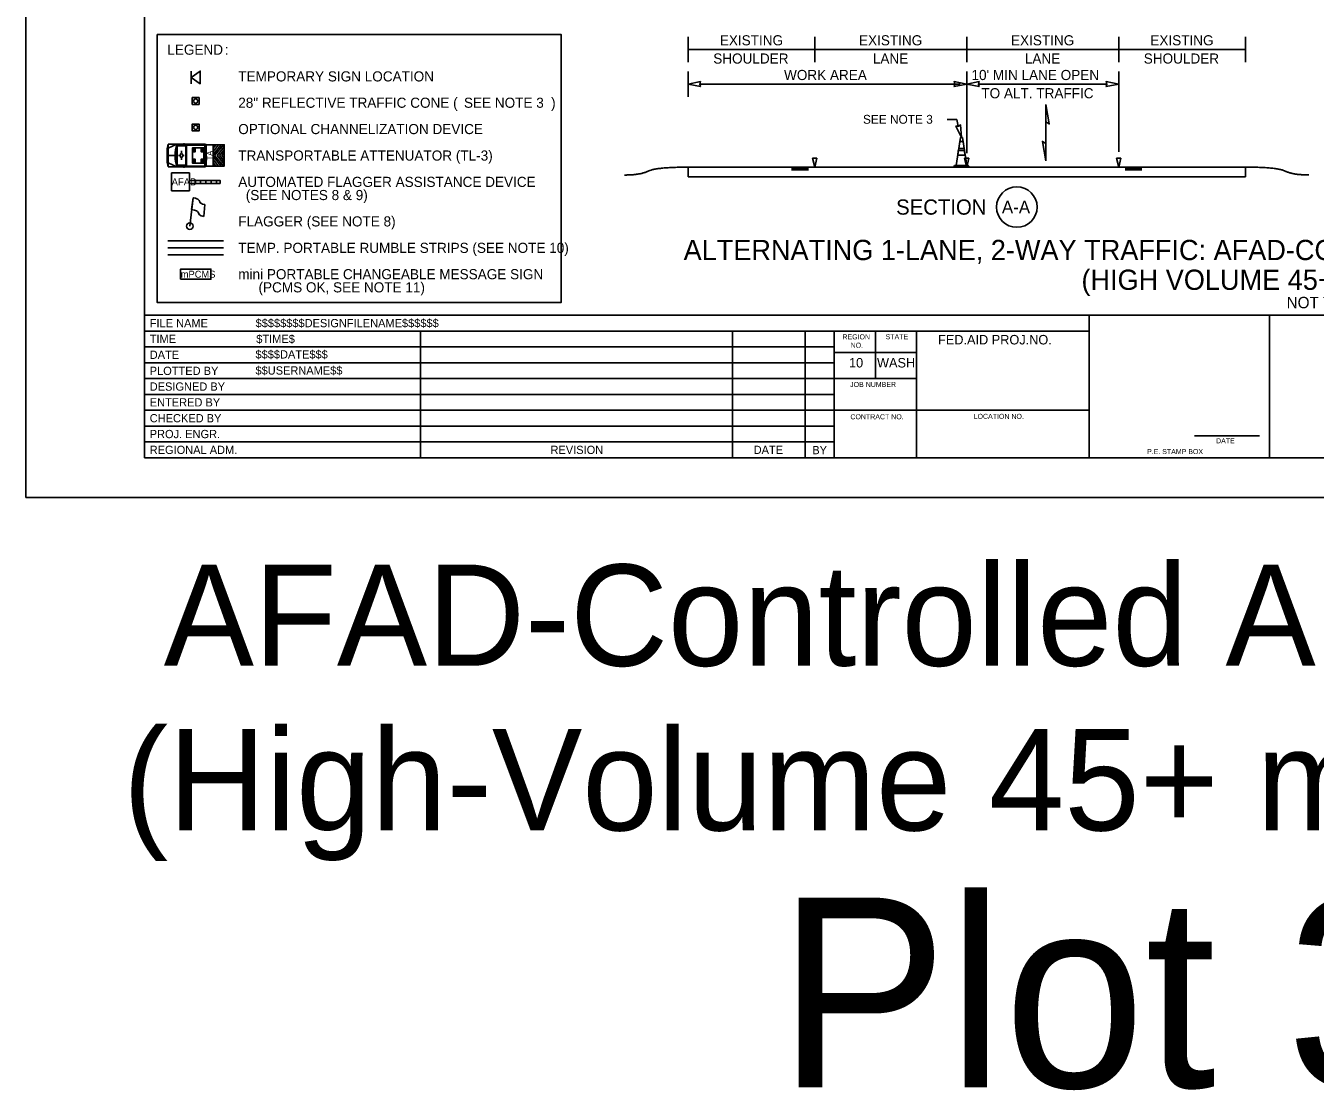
# Model space of a CAD drawing. Extents: x 99999.1 to 100095.7, y 99995 to 100010.7.
# Drawn here: x 100039.06 to 100049.24, y 99995.01 to 100003.41 of the extents above; entities that cross this region are included whole.
import ezdxf

# ---------------------------------------------------------------- set-up
doc = ezdxf.new("R2010")
doc.units = 0
for name, color, linetype in [('SH_DE_DetailHeading1Text', 7, 'Continuous'), ('SH_GI_PlotLimits', 7, 'Continuous'), ('SH_GI_SheetBorder', 7, 'Continuous'), ('SH_GI_SheetLocationText', 7, 'Continuous'), ('SH_GI_SheetTextInCells', 7, 'Continuous'), ('SH_GI_TitleBlockText', 7, 'Continuous'), ('TR_WZ_AFAD', 7, 'Continuous'), ('TR_WZ_FlaggingStation', 7, 'Continuous'), ('TR_WZ_PCMS', 7, 'Continuous'), ('TR_WZ_PortableSignMountBlk-Org', 7, 'Continuous'), ('TR_WZ_TrafficCone', 7, 'Continuous'), ('TR_WZ_TrafficConeElev', 7, 'Continuous'), ('TR_WZ_TransportableAttenuator', 7, 'Continuous'), ('TR_WZ_WorkZoneDetails', 7, 'Continuous'), ('TR_WZ_WorkZoneTextCurrent', 7, 'Continuous')]:
    doc.layers.add(name, color=color, linetype=linetype)

msp = doc.modelspace()

# ---------------------------------------------------------------- linework, layer by layer
at = {"layer": 'SH_GI_PlotLimits'}
msp.add_lwpolyline([(100039.062, 99999.687), (100056.062, 99999.687), (100056.062, 100010.687), (100039.062, 100010.687)], close=True, dxfattribs=at)
at = {"layer": 'SH_GI_SheetBorder'}
for p, q in [((100040, 100010.375), (100040, 100000)), ((100040, 100001.126), (100055.75, 100001.126)), ((100047.457, 100000), (100047.457, 100001.126)), ((100048.883, 100000), (100048.883, 100001.126)), ((100040, 100001.001), (100047.457, 100001.001)), ((100042.179, 100001.001), (100042.179, 100000)), ((100044.641, 100001.001), (100044.641, 100000)), ((100045.216, 100001.001), (100045.216, 100000)), ((100045.445, 100001.001), (100045.445, 100000)), ((100045.772, 100000.625), (100045.772, 100001.001)), ((100046.096, 100000), (100046.096, 100001.001)), ((100040, 100000.876), (100042.182, 100000.876)), ((100042.182, 100000.876), (100045.447, 100000.876)), ((100046.096, 100000.831), (100045.447, 100000.831)), ((100040, 100000.751), (100042.182, 100000.751)), ((100042.182, 100000.751), (100045.447, 100000.751)), ((100040, 100000.625), (100045.447, 100000.625)), ((100046.096, 100000.625), (100045.447, 100000.625)), ((100040, 100000.5), (100045.447, 100000.5)), ((100040, 100000.375), (100045.447, 100000.375)), ((100047.457, 100000.375), (100045.447, 100000.375)), ((100040, 100000.25), (100045.447, 100000.25)), ((100040, 100000.125), (100045.447, 100000.125)), ((100048.29, 100000.173), (100048.802, 100000.173)), ((100040, 100000), (100055.75, 100000))]:
    msp.add_line(p, q, dxfattribs=at)
at = {"layer": 'TR_WZ_AFAD'}
for p, q in [((100040.212, 100002.107), (100040.212, 100002.251)), ((100040.212, 100002.251), (100040.356, 100002.251)), ((100040.356, 100002.251), (100040.212, 100002.251)), ((100040.212, 100002.251), (100040.212, 100002.107)), ((100040.356, 100002.251), (100040.356, 100002.107)), ((100040.356, 100002.184), (100040.356, 100002.251)), ((100040.399, 100002.191), (100040.356, 100002.191)), ((100040.356, 100002.191), (100040.356, 100002.184)), ((100040.356, 100002.184), (100040.356, 100002.179)), ((100040.441, 100002.191), (100040.399, 100002.191)), ((100040.399, 100002.167), (100040.441, 100002.167)), ((100040.484, 100002.191), (100040.441, 100002.191)), ((100040.441, 100002.179), (100040.441, 100002.191)), ((100040.441, 100002.167), (100040.441, 100002.179)), ((100040.441, 100002.167), (100040.484, 100002.167)), ((100040.527, 100002.191), (100040.484, 100002.191)), ((100040.484, 100002.191), (100040.484, 100002.179)), ((100040.484, 100002.179), (100040.484, 100002.167)), ((100040.484, 100002.167), (100040.527, 100002.167)), ((100040.569, 100002.191), (100040.527, 100002.191)), ((100040.527, 100002.179), (100040.527, 100002.191)), ((100040.527, 100002.167), (100040.527, 100002.179)), ((100040.527, 100002.167), (100040.569, 100002.167)), ((100040.569, 100002.191), (100040.569, 100002.179)), ((100040.569, 100002.179), (100040.569, 100002.167)), ((100040.569, 100002.167), (100040.596, 100002.167)), ((100040.356, 100002.107), (100040.212, 100002.107)), ((100040.212, 100002.107), (100040.356, 100002.107))]:
    msp.add_line(p, q, dxfattribs=at)
for points in [[(100040.356, 100002.167), (100040.596, 100002.167), (100040.596, 100002.191), (100040.356, 100002.191)], [(100040.356, 100002.107), (100040.356, 100002.174), (100040.356, 100002.184)], [(100040.356, 100002.179), (100040.356, 100002.174), (100040.356, 100002.167), (100040.399, 100002.167)], [(100040.399, 100002.167), (100040.399, 100002.179), (100040.399, 100002.191)], [(100040.399, 100002.191), (100040.399, 100002.179), (100040.399, 100002.167)], [(100040.441, 100002.191), (100040.441, 100002.179), (100040.441, 100002.167)], [(100040.484, 100002.167), (100040.484, 100002.179), (100040.484, 100002.191)], [(100040.527, 100002.191), (100040.527, 100002.179), (100040.527, 100002.167)], [(100040.569, 100002.167), (100040.569, 100002.179), (100040.569, 100002.191)], [(100040.596, 100002.167), (100040.596, 100002.191), (100040.569, 100002.191)]]:
    msp.add_lwpolyline(points, dxfattribs=at)
at = {"layer": 'TR_WZ_FlaggingStation'}
for p, q in [((100040.357, 100001.829), (100040.383, 100002.053)), ((100040.372, 100001.962), (100040.383, 100002.054)), ((100040.372, 100001.962), (100040.372, 100001.962)), ((100040.477, 100001.999), (100040.467, 100001.906))]:
    msp.add_line(p, q, dxfattribs=at)
for points in [[(100040.383, 100002.054), (100040.387, 100002.053), (100040.402, 100002.05), (100040.413, 100002.046), (100040.42, 100002.042), (100040.427, 100002.038), (100040.432, 100002.032), (100040.435, 100002.026), (100040.436, 100002.021), (100040.44, 100002.014), (100040.449, 100002.008), (100040.458, 100002.004), (100040.477, 100001.999)], [(100040.467, 100001.906), (100040.46, 100001.907), (100040.446, 100001.91), (100040.433, 100001.919), (100040.428, 100001.927), (100040.425, 100001.935), (100040.418, 100001.944), (100040.409, 100001.949), (100040.395, 100001.955), (100040.372, 100001.962)]]:
    msp.add_lwpolyline(points, dxfattribs=at)
msp.add_circle((100040.357, 100001.829), 0.026, dxfattribs=at)
at = {"layer": 'TR_WZ_PCMS'}
msp.add_lwpolyline([(100040.284, 100001.41), (100040.524, 100001.41), (100040.524, 100001.49), (100040.284, 100001.49)], close=True, dxfattribs=at)
msp.add_lwpolyline([(100040.284, 100001.41), (100040.524, 100001.41), (100040.524, 100001.49), (100040.284, 100001.49), (100040.284, 100001.41)], dxfattribs=at)
at = {"layer": 'TR_WZ_PortableSignMountBlk-Org'}
msp.add_line((100040.368, 100002.954), (100040.368, 100003.054), dxfattribs=at)
msp.add_lwpolyline([(100040.368, 100003.004), (100040.44, 100003.054), (100040.44, 100002.954)], close=True, dxfattribs=at)
at = {"layer": 'TR_WZ_TrafficCone'}
for points in [[(100040.377, 100002.844), (100040.431, 100002.844), (100040.431, 100002.79), (100040.377, 100002.79), (100040.377, 100002.844)], [(100040.377, 100002.79), (100040.431, 100002.79), (100040.431, 100002.844), (100040.377, 100002.844), (100040.377, 100002.79)], [(100040.377, 100002.635), (100040.431, 100002.635), (100040.431, 100002.582), (100040.377, 100002.582), (100040.377, 100002.635)], [(100040.377, 100002.582), (100040.431, 100002.582), (100040.431, 100002.635), (100040.377, 100002.635), (100040.377, 100002.582)]]:
    msp.add_lwpolyline(points, dxfattribs=at)
for centre in [(100040.404, 100002.817), (100040.404, 100002.609)]:
    msp.add_circle(centre, 0.0167, dxfattribs=at)
at = {"layer": 'TR_WZ_TrafficConeElev'}
for p, q in [((100046.436, 100002.498), (100046.428, 100002.443)), ((100046.428, 100002.443), (100046.47, 100002.443)), ((100046.462, 100002.498), (100046.436, 100002.498)), ((100046.47, 100002.443), (100046.462, 100002.498)), ((100046.425, 100002.427), (100046.42, 100002.389)), ((100046.42, 100002.389), (100046.478, 100002.389)), ((100046.472, 100002.427), (100046.425, 100002.427)), ((100046.478, 100002.389), (100046.472, 100002.427)), ((100046.395, 100002.308), (100046.391, 100002.304)), ((100046.391, 100002.304), (100046.391, 100002.296)), ((100046.391, 100002.296), (100046.507, 100002.296)), ((100046.407, 100002.308), (100046.395, 100002.308)), ((100046.507, 100002.304), (100046.503, 100002.308)), ((100046.507, 100002.296), (100046.507, 100002.304))]:
    msp.add_line(p, q, dxfattribs=at)
msp.add_lwpolyline([(100046.407, 100002.308), (100046.491, 100002.308), (100046.457, 100002.529), (100046.441, 100002.529)], close=True, dxfattribs=at)
msp.add_lwpolyline([(100046.407, 100002.308), (100046.491, 100002.308), (100046.457, 100002.529), (100046.441, 100002.529)], close=True, dxfattribs=at)
msp.add_lwpolyline([(100046.503, 100002.308), (100046.491, 100002.308), (100046.407, 100002.308)], dxfattribs=at)
at = {"layer": 'TR_WZ_TransportableAttenuator'}
for p, q in [((100040.186, 100002.477), (100040.179, 100002.441)), ((100040.179, 100002.334), (100040.179, 100002.441)), ((100040.186, 100002.297), (100040.186, 100002.477)), ((100040.186, 100002.477), (100040.326, 100002.477)), ((100040.186, 100002.444), (100040.256, 100002.477)), ((100040.256, 100002.297), (100040.256, 100002.477)), ((100040.257, 100002.297), (100040.257, 100002.477)), ((100040.265, 100002.463), (100040.257, 100002.477)), ((100040.257, 100002.463), (100040.326, 100002.463)), ((100040.307, 100002.48), (100040.315, 100002.48)), ((100040.326, 100002.297), (100040.326, 100002.477)), ((100040.48, 100002.477), (100040.328, 100002.477)), ((100040.328, 100002.297), (100040.328, 100002.477)), ((100040.476, 100002.47), (100040.332, 100002.47)), ((100040.332, 100002.304), (100040.332, 100002.47)), ((100040.476, 100002.304), (100040.476, 100002.47)), ((100040.48, 100002.297), (100040.48, 100002.477)), ((100040.48, 100002.472), (100040.541, 100002.472)), ((100040.48, 100002.303), (100040.48, 100002.472)), ((100040.484, 100002.474), (100040.481, 100002.474)), ((100040.481, 100002.3), (100040.481, 100002.474)), ((100040.487, 100002.306), (100040.487, 100002.469)), ((100040.541, 100002.472), (100040.541, 100002.303)), ((100040.541, 100002.395), (100040.605, 100002.472)), ((100040.541, 100002.444), (100040.564, 100002.472)), ((100040.584, 100002.472), (100040.541, 100002.42)), ((100040.605, 100002.472), (100040.541, 100002.395)), ((100040.541, 100002.42), (100040.584, 100002.472)), ((100040.564, 100002.472), (100040.541, 100002.444)), ((100040.541, 100002.42), (100040.541, 100002.444)), ((100040.541, 100002.444), (100040.541, 100002.42)), ((100040.623, 100002.472), (100040.553, 100002.387)), ((100040.553, 100002.387), (100040.623, 100002.472)), ((100040.564, 100002.472), (100040.584, 100002.472)), ((100040.584, 100002.472), (100040.564, 100002.472)), ((100040.573, 100002.387), (100040.629, 100002.455)), ((100040.629, 100002.455), (100040.573, 100002.387)), ((100040.605, 100002.472), (100040.623, 100002.472)), ((100040.623, 100002.472), (100040.605, 100002.472)), ((100040.629, 100002.455), (100040.629, 100002.432)), ((100040.629, 100002.432), (100040.629, 100002.455)), ((100040.186, 100002.387), (100040.242, 100002.387)), ((100040.268, 100002.387), (100040.278, 100002.387)), ((100040.291, 100002.423), (100040.291, 100002.408)), ((100040.291, 100002.352), (100040.291, 100002.366)), ((100040.301, 100002.388), (100040.301, 100002.388)), ((100040.313, 100002.387), (100040.304, 100002.387)), ((100040.487, 100002.4), (100040.481, 100002.397)), ((100040.487, 100002.375), (100040.481, 100002.378)), ((100040.486, 100002.387), (100040.483, 100002.387)), ((100040.484, 100002.385), (100040.484, 100002.39)), ((100040.541, 100002.38), (100040.541, 100002.395)), ((100040.541, 100002.395), (100040.541, 100002.38)), ((100040.604, 100002.303), (100040.541, 100002.38)), ((100040.541, 100002.38), (100040.604, 100002.303)), ((100040.541, 100002.355), (100040.583, 100002.303)), ((100040.541, 100002.331), (100040.541, 100002.355)), ((100040.583, 100002.303), (100040.541, 100002.355)), ((100040.541, 100002.355), (100040.541, 100002.331)), ((100040.553, 100002.387), (100040.623, 100002.303)), ((100040.623, 100002.303), (100040.553, 100002.387)), ((100040.629, 100002.319), (100040.573, 100002.387)), ((100040.573, 100002.387), (100040.629, 100002.319)), ((100040.629, 100002.432), (100040.591, 100002.386)), ((100040.591, 100002.386), (100040.629, 100002.432)), ((100040.591, 100002.386), (100040.629, 100002.341)), ((100040.629, 100002.341), (100040.591, 100002.386)), ((100040.61, 100002.387), (100040.629, 100002.411)), ((100040.629, 100002.411), (100040.61, 100002.387)), ((100040.629, 100002.364), (100040.61, 100002.387)), ((100040.61, 100002.387), (100040.629, 100002.364)), ((100040.629, 100002.411), (100040.629, 100002.364)), ((100040.629, 100002.364), (100040.629, 100002.411)), ((100040.629, 100002.341), (100040.629, 100002.319)), ((100040.629, 100002.319), (100040.629, 100002.341)), ((100040.186, 100002.297), (100040.179, 100002.334)), ((100040.186, 100002.33), (100040.256, 100002.297)), ((100040.186, 100002.297), (100040.326, 100002.297)), ((100040.257, 100002.297), (100040.266, 100002.311)), ((100040.257, 100002.311), (100040.326, 100002.311)), ((100040.307, 100002.295), (100040.315, 100002.295)), ((100040.48, 100002.297), (100040.328, 100002.297)), ((100040.476, 100002.304), (100040.332, 100002.304)), ((100040.48, 100002.303), (100040.541, 100002.303)), ((100040.484, 100002.3), (100040.481, 100002.3)), ((100040.564, 100002.303), (100040.541, 100002.331)), ((100040.541, 100002.331), (100040.564, 100002.303)), ((100040.583, 100002.303), (100040.564, 100002.303)), ((100040.564, 100002.303), (100040.583, 100002.303)), ((100040.623, 100002.303), (100040.604, 100002.303)), ((100040.604, 100002.303), (100040.623, 100002.303))]:
    msp.add_line(p, q, dxfattribs=at)
for points in [[(100040.468, 100002.327), (100040.378, 100002.327), (100040.378, 100002.447), (100040.468, 100002.447)], [(100040.386, 100002.417), (100040.401, 100002.417), (100040.401, 100002.44), (100040.386, 100002.44)], [(100040.461, 100002.417), (100040.446, 100002.417), (100040.446, 100002.44), (100040.461, 100002.44)], [(100040.541, 100002.472), (100040.629, 100002.472), (100040.629, 100002.303), (100040.541, 100002.303)], [(100040.386, 100002.335), (100040.401, 100002.335), (100040.401, 100002.357), (100040.386, 100002.357)], [(100040.461, 100002.335), (100040.446, 100002.335), (100040.446, 100002.357), (100040.461, 100002.357)]]:
    msp.add_lwpolyline(points, close=True, dxfattribs=at)
msp.add_lwpolyline([(100040.541, 100002.303), (100040.629, 100002.303), (100040.629, 100002.472), (100040.541, 100002.472)], dxfattribs=at)
for centre, major_axis, start_param, end_param in [((100040.356, 100002.387), (0, -0.189), 4.215852, 5.209111), ((100040.484, 100002.469), (0, 0.00549), 4.712389, 6.283185), ((100040.484, 100002.306), (0, -0.00549), 6.283185, 7.853982)]:
    msp.add_ellipse(centre, major_axis=major_axis, ratio=0.60201, start_param=start_param, end_param=end_param, dxfattribs=at)
for centre, major_axis in [((100040.291, 100002.387), (0, 0.0173)), ((100040.484, 100002.387), (0, 0.00254))]:
    msp.add_ellipse(centre, major_axis=major_axis, ratio=0.60201, dxfattribs=at)
at = {"layer": 'TR_WZ_WorkZoneDetails'}
for p, q in [((100044.291, 100003.125), (100044.291, 100003.325)), ((100045.291, 100003.125), (100045.291, 100003.325)), ((100046.491, 100003.125), (100046.491, 100003.325)), ((100047.691, 100003.125), (100047.691, 100003.325)), ((100048.691, 100003.125), (100048.691, 100003.325)), ((100044.291, 100003.225), (100045.291, 100003.225)), ((100045.291, 100003.225), (100046.491, 100003.225)), ((100046.491, 100003.225), (100047.691, 100003.225)), ((100047.691, 100003.225), (100048.691, 100003.225)), ((100044.291, 100002.851), (100044.291, 100003.051)), ((100046.491, 100002.405), (100046.491, 100003.051)), ((100047.691, 100002.415), (100047.691, 100003.051)), ((100046.439, 100002.951), (100044.384, 100002.951)), ((100047.597, 100002.951), (100046.584, 100002.951)), ((100046.336, 100002.672), (100046.412, 100002.672)), ((100046.425, 100002.62), (100046.412, 100002.672)), ((100047.116, 100002.652), (100047.116, 100002.483)), ((100047.116, 100002.483), (100047.116, 100002.652)), ((100044.291, 100002.295), (100044.291, 100002.22)), ((100048.691, 100002.295), (100044.291, 100002.295)), ((100045.108, 100002.29), (100045.241, 100002.29)), ((100045.108, 100002.285), (100045.241, 100002.285)), ((100045.108, 100002.279), (100045.241, 100002.279)), ((100045.108, 100002.274), (100045.241, 100002.274)), ((100047.874, 100002.29), (100047.741, 100002.29)), ((100047.874, 100002.284), (100047.741, 100002.284)), ((100047.874, 100002.278), (100047.741, 100002.278)), ((100047.874, 100002.273), (100047.741, 100002.273)), ((100048.691, 100002.295), (100048.691, 100002.22)), ((100048.691, 100002.22), (100044.291, 100002.22)), ((100040.624, 100001.714), (100040.184, 100001.714)), ((100040.624, 100001.659), (100040.184, 100001.659)), ((100040.624, 100001.603), (100040.184, 100001.603))]:
    msp.add_line(p, q, dxfattribs=at)
for points in [[(100044.291, 100002.951), (100044.389, 100002.932), (100044.384, 100002.951), (100044.389, 100002.971)], [(100046.491, 100002.951), (100046.392, 100002.932), (100046.397, 100002.951), (100046.392, 100002.971)], [(100046.491, 100002.951), (100046.589, 100002.932), (100046.584, 100002.951), (100046.589, 100002.971)], [(100047.691, 100002.951), (100047.592, 100002.932), (100047.597, 100002.951), (100047.592, 100002.971)], [(100047.116, 100002.789), (100047.143, 100002.636), (100047.116, 100002.652)], [(100046.449, 100002.529), (100046.406, 100002.619), (100046.426, 100002.62), (100046.443, 100002.629)], [(100047.116, 100002.345), (100047.089, 100002.499), (100047.116, 100002.483)], [(100045.291, 100002.295), (100045.274, 100002.365), (100045.307, 100002.365)], [(100046.491, 100002.295), (100046.474, 100002.365), (100046.507, 100002.365)], [(100047.691, 100002.295), (100047.674, 100002.365), (100047.707, 100002.365)]]:
    msp.add_lwpolyline(points, close=True, dxfattribs=at)
for points in [[(100045.307, 100002.365), (100045.274, 100002.365), (100045.291, 100002.295), (100045.307, 100002.365)], [(100046.507, 100002.365), (100046.474, 100002.365), (100046.491, 100002.295), (100046.507, 100002.365)], [(100047.707, 100002.365), (100047.674, 100002.365), (100047.691, 100002.295), (100047.707, 100002.365)]]:
    msp.add_lwpolyline(points, dxfattribs=at)
msp.add_circle((100046.887, 100001.98), 0.16, dxfattribs=at)
for points in [[(100044.291, 100002.295), (100044.04, 100002.295), (100043.914, 100002.233), (100043.789, 100002.233)], [(100048.691, 100002.295), (100048.942, 100002.296), (100049.067, 100002.233), (100049.193, 100002.234)]]:
    msp.add_open_spline(points, degree=2, dxfattribs=at)
at = {"layer": 'TR_WZ_WorkZoneTextCurrent'}
msp.add_lwpolyline([(100040.1, 100003.343), (100043.289, 100003.343), (100043.289, 100001.226), (100040.1, 100001.226)], close=True, dxfattribs=at)

# ---------------------------------------------------------------- texts
at = {"layer": 'SH_DE_DetailHeading1Text'}
for s, height, p in [('ALTERNATING 1-LANE, 2-WAY TRAFFIC: AFAD-CONTROLLED + TEMPORARY RUMBLE STRIPS', 0.16, (100044.256, 100001.561)), ('(HIGH VOLUME 45+ MPH HIGHWAYS)', 0.16, (100047.397, 100001.326)), ('NOT TO SCALE', 0.09, (100049.017, 100001.181))]:
    msp.add_text(s, height=height, rotation=360, dxfattribs=at).set_placement(p)
at = {"layer": 'SH_GI_SheetLocationText'}
for s, height, p in [('AFAD-Controlled Alt Traffic + RS', 0.8, (100040.151, 99998.357)), ('(High-Volume 45+ mph Highways)', 0.8, (100039.83, 99997.057)), ('Plot 3', 1.5, (100045.001, 99995.027))]:
    msp.add_text(s, height=height, dxfattribs=at).set_placement(p)
at = {"layer": 'SH_GI_SheetTextInCells'}
for s, height, p in [('FILE NAME', 0.0651, (100040.041, 100001.031)), ('TIME', 0.0651, (100040.041, 100000.906)), ('REGION', 0.04, (100045.51, 100000.935)), ('STATE', 0.04, (100045.851, 100000.936)), ('FED.AID PROJ.NO.', 0.07506, (100046.265, 100000.895)), ('DATE', 0.0651, (100040.041, 100000.781)), ('NO.', 0.04, (100045.575, 100000.869)), ('PLOTTED BY', 0.0651, (100040.041, 100000.654)), ('10', 0.0751, (100045.562, 100000.713)), ('WASH', 0.0751, (100045.783, 100000.713)), ('DESIGNED BY', 0.06505, (100040.041, 100000.53)), ('JOB NUMBER', 0.04, (100045.571, 100000.559)), ('ENTERED BY', 0.0651, (100040.041, 100000.405)), ('CHECKED BY', 0.0651, (100040.041, 100000.28)), ('CONTRACT NO.', 0.04003, (100045.573, 100000.304)), ('LOCATION NO.', 0.04003, (100046.546, 100000.307)), ('PROJ. ENGR.', 0.06505, (100040.041, 100000.155)), ('DATE', 0.04, (100048.46, 100000.114)), ('REGIONAL ADM.', 0.06505, (100040.041, 100000.03)), ('REVISION', 0.0651, (100043.205, 100000.03)), ('DATE', 0.0651, (100044.809, 100000.03)), ('BY', 0.0651, (100045.272, 100000.028)), ('P.E. STAMP BOX', 0.04003, (100047.915, 100000.029))]:
    msp.add_text(s, height=height, dxfattribs=at).set_placement(p)
at = {"layer": 'SH_GI_TitleBlockText'}
for s, height, p in [('$$$$$$$$DESIGNFILENAME$$$$$$', 0.06505, (100040.877, 100001.031)), ('$TIME$', 0.0651, (100040.882, 100000.906)), ('$$$$DATE$$$', 0.06505, (100040.876, 100000.784)), ('$$USERNAME$$', 0.06505, (100040.876, 100000.657))]:
    msp.add_text(s, height=height, dxfattribs=at).set_placement(p)
at = {"layer": 'TR_WZ_AFAD'}
msp.add_text('AFAD', height=0.056, dxfattribs=at).set_placement((100040.214, 100002.151))
at = {"layer": 'TR_WZ_PCMS'}
msp.add_text('mPCMS', height=0.055, rotation=360, dxfattribs=at).set_placement((100040.286, 100001.422))
at = {"layer": 'TR_WZ_TransportableAttenuator'}
msp.add_text('TA', height=0.045, rotation=90, dxfattribs=at).set_placement((100040.537, 100002.348))
at = {"layer": 'TR_WZ_WorkZoneDetails'}
for s, height, p in [('EXISTING', 0.08, (100044.542, 100003.257)), ('EXISTING', 0.08, (100045.641, 100003.257)), ('EXISTING', 0.08, (100046.841, 100003.257)), ('EXISTING', 0.08, (100047.941, 100003.257)), ('SHOULDER', 0.08, (100044.49, 100003.113)), ('LANE', 0.08, (100045.75, 100003.113)), ('LANE', 0.08, (100046.95, 100003.113)), ('SHOULDER', 0.08, (100047.889, 100003.113)), ('SECTION', 0.12, (100045.934, 100001.92)), ('A-A', 0.1, (100046.769, 100001.93))]:
    msp.add_text(s, height=height, rotation=360, dxfattribs=at).set_placement(p)
for s, p in [('WORK AREA', (100045.049, 100002.983)), ("10' MIN LANE OPEN", (100046.529, 100002.983)), ('TO ALT. TRAFFIC', (100046.607, 100002.839))]:
    msp.add_text(s, height=0.08, dxfattribs=at).set_placement(p)
at = {"layer": 'TR_WZ_WorkZoneTextCurrent'}
for s, p in [('LEGEND', (100040.18, 100003.183)), (':', (100040.633, 100003.183)), ('TEMPORARY SIGN LOCATION ', (100040.74, 100002.972)), ('28" REFLECTIVE TRAFFIC CONE (', (100040.74, 100002.764)), (')', (100043.21, 100002.764)), ('SEE NOTE 3', (100042.522, 100002.764)), ('OPTIONAL CHANNELIZATION DEVICE', (100040.74, 100002.556)), ('TRANSPORTABLE ATTENUATOR (TL-3)', (100040.74, 100002.347)), ('AUTOMATED FLAGGER ASSISTANCE DEVICE', (100040.74, 100002.139)), ('  (SEE NOTES 8 & 9)', (100040.74, 100002.035)), ('FLAGGER (SEE NOTE 8)', (100040.74, 100001.827)), ('TEMP. PORTABLE RUMBLE STRIPS (SEE NOTE 10)', (100040.74, 100001.618)), ('mini PORTABLE CHANGEABLE MESSAGE SIGN', (100040.74, 100001.41)), ('(PCMS OK, SEE NOTE 11)', (100040.9, 100001.306))]:
    msp.add_text(s, height=0.08, rotation=360, dxfattribs=at).set_placement(p)
msp.add_text('SEE NOTE 3', height=0.07, dxfattribs=at).set_placement((100045.672, 100002.638))

doc.saveas('drawing.dxf')
